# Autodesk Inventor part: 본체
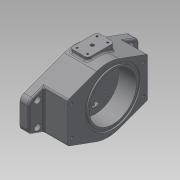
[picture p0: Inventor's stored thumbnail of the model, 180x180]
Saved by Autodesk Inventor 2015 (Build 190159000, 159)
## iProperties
Created: 2023-11
Part Number: 본체
Material: 일반
Document SubType Name: Modeling
Designer: user
Density: 1 g/cm^3
Appearance: 기본값
Author: user
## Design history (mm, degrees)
sketch "스케치1"
  geometry: L1 (94, 45.732)-(94, -45.732); L2 (-94, -45.732)-(-94, 45.732); L3 (-94, 45.732)-(94, -45.732); L4 (94, 45.732)-(-94, -45.732); L5 (18.811, -51.683)-(94, -24.317); L6 (94, 24.317)-(18.811, 51.683); L7 (-94, -24.317)-(-18.811, -51.683); L8 (-94, 24.317)-(-18.811, 51.683); L9 (180.191, 0)-(-186.924, 0); A1 r 55 centre (0, 0) between (18.811, 51.683) and (-18.811, 51.683); 1 further point
  constraints: 18 end point, 4 point on circle, 4 point on line, 4 tangent, 2 midpoint, 1 centre point, 1 coincident, 1 horizontal, 1 parallel, 2 other
  dimensions: "d0" = 188 distance of L2.end L1.start; "d1" = 110 diameter of A1; "d2" = 40 deg angle of L5 L6; "d3" = 40 deg angle of L8 L7
extrude "돌출1" new body sketch "스케치1" distance "d4" = 55; taper "d5" = 0 deg
sketch "스케치2"
  geometry: L1 (-50, 98)-(50, 98); L2 (50, 98)-(50, 68); L3 (50, 68)-(-50, 68); L4 (-50, 68)-(-50, 98); L5 (-50, -68)-(50, -68); L6 (50, -68)-(50, -98); L7 (50, -98)-(-50, -98); L8 (-50, -98)-(-50, -68); A1 r 55 centre (0, 0) between (-51.683, 18.811) and (-51.683, -18.811) reference; 2 further points
  constraints: 16 end point, 4 parallel, 2 horizontal, 2 midpoint, 2 perpendicular, 2 vertical alignment
  dimensions: "d6" = 136 distance between parallel lines of L5 L3; "d7" = 100 distance of L2.end L3.end; "d8" = 100 distance of L5.start L5.end; "d9" = 30 distance of L1.end L2.end; "d10" = 30 distance of L5.end L6.end; "d11" = 68 distance from line of A1.centre L3
extrude "돌출2" cut sketch "스케치2" distance "d12" = 40; taper "d13" = 0 deg
sketch "스케치3"
  geometry: 2 further points
  dimensions: "d15" = 79 vertical distance of point (0, 0) point (20, 79); "d16" = 20 horizontal distance of point (0, 0) point (20, 79)
hole "구멍1" sketch "스케치3" at (20, 79) diameter "d17" = 6.6; stored, may be unused: countersink angle "d21" = 90 deg, drill point angle "d23" = 118 deg; dims "d18" = 6, "d19" = 11, "d20" = 6.6, "d22" = 8
fillet "모깎기1" dims "d24" = 10
sketch "스케치4"
  geometry: C1 r 40 at (0, 9); A1 r 55 centre (0, 0) between (-51.683, 18.811) and (-51.683, -18.811) reference
  constraints: 1 centre point
  dimensions: "d118" = 80 diameter of C1; "d119" = 9 distance of A1.centre C1.centre
extrude "돌출3" cut sketch "스케치4" distance "d26" = 30; taper "d27" = 0 deg
node "작업 평면1"
sketch "스케치9"
  geometry: L1 (5, -14)-(35, -14); L2 (35, -14)-(35, 32); L3 (35, 32)-(5, 32); L4 (5, 32)-(5, -14); L5 (0, -18.811)-(0, 18.811) reference; L6 (0, 87.42)-(0, 18.811) reference; 1 further point
  constraints: 8 end point, 2 parallel, 1 horizontal, 1 perpendicular
  dimensions: "d46" = 46 distance of L1.end L2.end; "d47" = 30 distance of L2.end L3.end; "d154" = 5 distance between parallel lines of L6 L4; "d155" = 32 distance from line of point (0, 0) L3
extrude "돌출7" join sketch "스케치9" stored distance "d49" = 5; taper "d50" = 0 deg
sketch "스케치12"
  geometry: L1 (0, 67.56)-(0, 0) reference; L2 (-55, 51.094)-(-55, 16.465) reference; 3 further points
  constraints: 1 horizontal alignment, 1 midpoint, 1 other
  dimensions: "d68" = 15 distance from line of L1 point (-15, 33.78)
feature "엠보싱1" sketch "스케치12" dims "d69" = 0.5, "d70" = 0
fillet "모깎기8" dims "d114" = 5
fillet "모깎기9" dims "d115" = 5
fillet "모깎기10" dims "d116" = 3
fillet "모깎기11" dims "d117" = 3
sketch "스케치17"
  geometry: C1 r 40 at (0, 9) reference; C2 r 47.5 at (0, 9); C3 r 43.4 at (0, 9)
  constraints: 2 centre point, 2 coincident
  dimensions: "d120" = 95 diameter of C2; "d121" = 86.8 diameter of C3
extrude "돌출11" cut sketch "스케치17" distance "d122" = 2.4; taper "d123" = 0 deg
fillet "모깎기12" dims "d124" = 0.5
sketch "스케치18"
  geometry: C1 r 10 at (0, -9); 1 further point
  constraints: 1 centre point, 1 coincident
  dimensions: "d192" = 20 diameter of C1
extrude "돌출12" cut sketch "스케치18" distance "d125" = 10; taper "d126" = 0 deg
sketch "스케치19"
  geometry: C1 r 10 at (0, 0) reference; C2 r 17.5 at (0, 0)
  constraints: 1 centre point, 1 coincident
  dimensions: "d127" = 35 diameter of C2
extrude "돌출13" join sketch "스케치19" distance "d128" = 5; taper "d129" = 0 deg
sketch "스케치20"
  geometry: C1 r 17.5 at (0, 0) reference
hole "구멍6" sketch "스케치20" at (0, 0) diameter "d130" = 16; stored, may be unused: countersink angle "d134" = 90 deg, drill point angle "d136" = 118 deg; dims "d131" = 32, "d132" = 25, "d133" = 8.4, "d135" = 41.3
chamfer "모따기3" distance "d137" = 0.4; stored, may be unused: second distance "d138" = 2, angle "d139" = 30 deg
chamfer "모따기4" distance "d140" = 1; stored, may be unused: second distance "d141" = 2, angle "d142" = 30 deg
fillet "모깎기13" dims "d143" = 0.2
sketch "스케치21"
  geometry: L1 (-32.5, -6)-(32.5, -6); L2 (32.5, -6)-(32.5, 6); L3 (32.5, 6)-(-32.5, 6); L4 (-32.5, 6)-(-32.5, -6); L5 (-32.5, -6)-(32.5, 6); L6 (32.5, -6)-(-32.5, 6); C1 r 40 at (0, 0) reference; C2 r 10 at (0, -9) reference; A1 r 29 centre (0, 0) between (-28.373, 6) and (-28.373, -6); A2 r 29 centre (0, 0) between (28.373, -6) and (28.373, 6); A3 r 24 centre (0, -9) between (23.812, -6) and (18.735, 6); A4 r 24 centre (0, -9) between (-18.735, 6) and (-23.812, -6)
  constraints: 12 end point, 8 point on circle, 8 point on line, 4 centre point, 2 coincident, 2 midpoint, 2 parallel, 1 horizontal, 1 perpendicular
  dimensions: "d146" = 12 distance of L1.end L2.end; "d147" = 65 distance of L2.end L3.end; "d148" = 29 radius of A2; "d150" = 29 radius of A1
extrude "돌출14" cut sketch "스케치21" distance "d152" = 12; taper "d153" = 0 deg
sketch "스케치22"
  geometry: L1 (30, 32)-(10, 32) reference; L2 (29, -8)-(11, -8); L3 (11, -8)-(11, 26); L4 (11, 26)-(29, 26); L5 (29, 26)-(29, -8); L6 (29, -8)-(11, 26); L7 (11, -8)-(29, 26); L8 (0, 87.42)-(0, 18.811) reference; 6 further points
  constraints: 12 end point, 3 coincident, 2 midpoint, 2 parallel, 1 horizontal, 1 perpendicular
  dimensions: "d156" = 18 distance of L3.end L4.end; "d157" = 20 distance from line of L8 point (20, 9); "d158" = 34 distance of L4.end L2.start; "d159" = 6 distance between parallel lines of L1 L4
hole "구멍7" sketch "스케치22" at (29, 26), (11, 26), (11, -8), (29, -8) diameter "d160" = 3.242; stored, may be unused: countersink angle "d164" = 90 deg, drill point angle "d166" = 118 deg; dims "d161" = 8, "d162" = 25, "d163" = 8.4, "d165" = 10
sketch "스케치23"
  geometry: L1 (0, 87.42)-(0, 18.811) reference; C1 r 3 at (20, 9); 1 further point
  constraints: 1 centre point
  dimensions: "d167" = 6 diameter of C1; "d168" = 9 vertical distance of point (0, 0) C1.centre; "d169" = 20 distance from line of L1 C1.centre
extrude "돌출15" cut sketch "스케치23" stored distance "d170" = 12; taper "d171" = 0 deg
sketch "스케치24"
  geometry: A1 r 29 centre (0, 0) between (28.373, -6) and (28.373, 6) reference; 1 further point
  dimensions: "d172" = 15 horizontal distance of A1.centre point (15, 17); "d173" = 17 vertical distance of A1.centre point (15, 17)
hole "구멍8" sketch "스케치24" at (15, 17) diameter "d174" = 3.242; stored, may be unused: countersink angle "d178" = 90 deg, drill point angle "d180" = 118 deg; dims "d175" = 8, "d176" = 25, "d177" = 8.4, "d179" = 10
sketch "스케치25"
  geometry: A1 r 55 centre (0, 0) between (-51.683, 18.811) and (-51.683, -18.811) reference; 1 further point
  dimensions: "d181" = 61 vertical distance of A1.centre point (25, -61); "d182" = 25 horizontal distance of A1.centre point (25, -61)
hole "구멍9" sketch "스케치25" at (25, -61) diameter "d183" = 4.917; stored, may be unused: countersink angle "d187" = 90 deg, drill point angle "d189" = 118 deg; dims "d184" = 12, "d185" = 25, "d186" = 8.4, "d188" = 14
fillet "모깎기14" dims "d190" = 2
fillet "모깎기15" dims "d191" = 2
node "솔리드1"
mirror "대칭1"
mirror "대칭2"
mirror "대칭3"
mirror "대칭8"
mirror "대칭9"
mirror "대칭10"
mirror "대칭11"
other parameters: "d45" = 59, "d53" = 48, "d54" = 58, "d144" = 48, "d145" = 58, "d193" = 48
